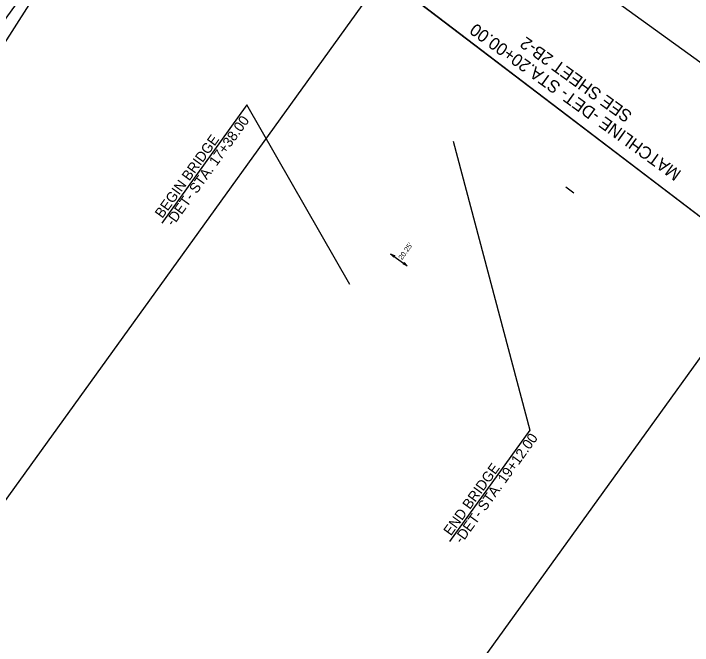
# Model space of a CAD drawing. Extents: x 2189185 to 2191058, y 386509 to 388561.
# Drawn here: x 2189944 to 2190612, y 387535 to 388157 of the extents above; entities that cross this region are included whole.
import ezdxf

# ---------------------------------------------------------------- set-up
doc = ezdxf.new("R2010")
doc.units = 0
for name, color, linetype in [('Matchline', 7, 'Continuous'), ('Matchline Text', 7, 'Continuous'), ('Prop Dimension', 7, 'Continuous'), ('Prop Dimension Text', 7, 'Continuous'), ('Prop RDY Alternate Text Yellow', 7, 'Continuous'), ('Prop Terminator CELL', 7, 'Continuous'), ('Sheet Clip Boundary CELL', 7, 'Continuous'), ('Sheet Layout Plan Border', 7, 'Continuous'), ('Sheet Title CELL', 7, 'Continuous')]:
    doc.layers.add(name, color=color, linetype=linetype)

msp = doc.modelspace()

# ---------------------------------------------------------------- linework, layer by layer
at = {"layer": 'Matchline'}
msp.add_line((2190256.9, 388232.77), (2190718.7, 387881.07), dxfattribs=at)
at = {"layer": 'Prop Dimension'}
msp.add_line((2190314.54, 387920.44), (2190330.97, 387908.59), dxfattribs=at)
at = {"layer": 'Prop RDY Alternate Text Yellow'}
msp.add_line((2190486.85, 387986.23), (2190494.96, 387980.38), dxfattribs=at)
at = {"layer": 'Prop Terminator CELL'}
for points in [[(2190317.73, 387917.18), (2190314.54, 387920.44), (2190318.67, 387918.44), (2190317.74, 387918.13)], [(2190327.77, 387911.85), (2190330.97, 387908.59), (2190326.83, 387910.59), (2190327.77, 387910.9)]]:
    msp.add_lwpolyline(points, close=True, dxfattribs=at)
at = {"layer": 'Sheet Clip Boundary CELL'}
msp.add_lwpolyline([(2190166.8, 386710.01), (2190905.33, 387738.93), (2190256.9, 388232.77), (2190233.39, 388201.76), (2190061.07, 388326.03), (2189853.58, 388001.31), (2189912.61, 387915.43), (2189757.61, 387710.51), (2189654.64, 387750.49), (2189330.08, 387312.42)], close=True, dxfattribs=at)
at = {"layer": 'Sheet Layout Plan Border'}
for points in [[(2190188.92, 387222.15), (2189805.85, 387498.41), (2190526.13, 388497.18), (2190654.9, 388404.31), (2190753.52, 388541.06), (2191007.82, 388357.66)], [(2190181.72, 386698.24), (2191000.63, 387833.76), (2190320.53, 388324.24), (2190209.82, 388170.73), (2190038.29, 388294.44), (2189330.08, 387312.42)]]:
    msp.add_lwpolyline(points, close=True, dxfattribs=at)
at = {"layer": 'Sheet Title CELL'}
for p, q in [((2190173.22, 388066.91), (2190089.44, 387950.81)), ((2190274.3, 387890.29), (2190173.22, 388066.91)), ((2190376.07, 388031.41), (2190451.6, 387746.96)), ((2190451.6, 387746.96), (2190372.59, 387637.46))]:
    msp.add_line(p, q, dxfattribs=at)

# ---------------------------------------------------------------- texts
at = {"layer": 'Matchline Text'}
for s, p in [('MATCHLINE -DET- STA.20+00.00', (2190601.45, 388001.33)), ('SEE SHEET 2B-2', (2190553.21, 388058.58))]:
    msp.add_text(s, height=12.15, rotation=144.20184, dxfattribs=at).set_placement(p)
at = {"layer": 'Prop Dimension Text'}
msp.add_text("20.25'", height=5, rotation=54.20184, dxfattribs=at).set_placement((2190325.77, 387914.08))
at = {"layer": 'Sheet Title CELL'}
for s, p in [('-DET- STA. 17+38.00', (2190100.6, 387947.07)), ('BEGIN BRIDGE', (2190089.9, 387954.79)), ('-DET- STA. 19+12.00', (2190384.51, 387634.85)), ('END BRIDGE', (2190373.82, 387642.56))]:
    msp.add_text(s, height=10, rotation=54.18603, dxfattribs=at).set_placement(p)

doc.saveas('drawing.dxf')
